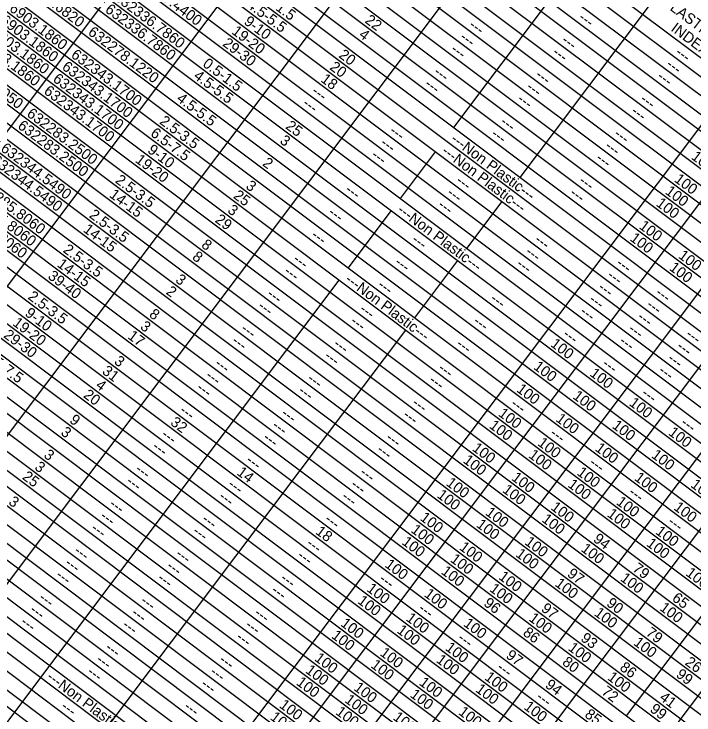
# Model space of a CAD drawing. Extents: x 627484.2 to 627517.5, y 367968.7 to 367996.9.
# Drawn here: x 627492.236 to 627495.744, y 367986.94 to 367990.557 of the extents above; entities that cross this region are included whole.
import ezdxf

# ---------------------------------------------------------------- set-up
doc = ezdxf.new("R2010")
doc.units = 0
doc.layers.add('Default', color=7, linetype='Continuous')

msp = doc.modelspace()

# ---------------------------------------------------------------- linework, layer by layer
at = {"layer": 'Default'}
for p, q in [((627492.9586, 367992.4496), (627498.2015, 367988.5126)), ((627492.9118, 367992.3872), (627498.1547, 367988.4503)), ((627492.8649, 367992.3248), (627498.1078, 367988.3879)), ((627492.8181, 367992.2625), (627498.061, 367988.3255)), ((627492.7771, 367992.2079), (627498.02, 367988.2709)), ((627492.7303, 367992.1455), (627497.9732, 367988.2086)), ((627490.4128, 367987.5698), (627493.8348, 367992.127)), ((627492.6834, 367992.0832), (627497.9263, 367988.1462)), ((627492.6425, 367992.0286), (627497.8854, 367988.0916)), ((627492.5956, 367991.9662), (627497.8385, 367988.0293)), ((627492.5488, 367991.9038), (627497.7917, 367987.9669)), ((627490.7966, 367987.2816), (627494.2186, 367991.8387)), ((627492.5019, 367991.8415), (627497.7449, 367987.9045)), ((627492.461, 367991.7869), (627497.7039, 367987.8499)), ((627492.4141, 367991.7245), (627497.657, 367987.7876)), ((627492.3673, 367991.6621), (627497.6102, 367987.7252)), ((627492.3263, 367991.6076), (627497.5692, 367987.6706)), ((627492.6599, 367988.9917), (627494.589, 367991.5606)), ((627492.2795, 367991.5452), (627497.5224, 367987.6082)), ((627492.2326, 367991.4828), (627497.4755, 367987.5459)), ((627492.1858, 367991.4204), (627497.4287, 367987.4835)), ((627492.139, 367991.3581), (627497.3819, 367987.4211)), ((627492.0921, 367991.2957), (627497.335, 367987.3587)), ((627493.0263, 367988.7165), (627494.9554, 367991.2855)), ((627492.0511, 367991.2411), (627497.2941, 367987.3042)), ((627492.0043, 367991.1787), (627497.2472, 367987.2418)), ((627491.9575, 367991.1164), (627497.2004, 367987.1794)), ((627491.9165, 367991.0618), (627497.1594, 367987.1248)), ((627491.8697, 367990.9994), (627497.1126, 367987.0625)), ((627494.5052, 367989.9714), (627495.2428, 367990.9538)), ((627491.8287, 367990.9448), (627497.0716, 367987.0079)), ((627491.7818, 367990.8825), (627497.0247, 367986.9455)), ((627491.735, 367990.8201), (627496.9779, 367986.8832)), ((627491.6882, 367990.7577), (627496.9311, 367986.8208)), ((627491.6413, 367990.6954), (627496.8842, 367986.7584)), ((627494.8482, 367989.7138), (627495.5859, 367990.6962)), ((627491.6003, 367990.6408), (627496.8433, 367986.7038)), ((627491.5535, 367990.5784), (627496.7964, 367986.6415)), ((627491.5067, 367990.516), (627496.7496, 367986.5791)), ((627491.4657, 367990.4615), (627496.7086, 367986.5245)), ((627494.1802, 367987.85), (627496.1093, 367990.419)), ((627491.4189, 367990.3991), (627496.6618, 367986.4621)), ((627491.372, 367990.3367), (627496.6149, 367986.3998)), ((627491.331, 367990.2821), (627496.5739, 367986.3452)), ((627491.2842, 367990.2198), (627496.5271, 367986.2828)), ((627491.2374, 367990.1574), (627496.4803, 367986.2204)), ((627494.3673, 367987.7095), (627496.191, 367990.1382)), ((627491.1905, 367990.095), (627496.4334, 367986.1581)), ((627491.1495, 367990.0404), (627496.3925, 367986.1035)), ((627491.1027, 367989.9781), (627496.3456, 367986.0411)), ((627494.5856, 367987.5456), (627496.4093, 367989.9742)), ((627491.0559, 367989.9157), (627496.2988, 367985.9787)), ((627491.009, 367989.8533), (627496.2519, 367985.9164)), ((627494.23, 367989.605), (627494.4115, 367989.8467)), ((627494.7728, 367987.4051), (627496.5965, 367989.8337)), ((627490.9622, 367989.791), (627496.2051, 367985.854)), ((627490.9212, 367989.7364), (627496.1641, 367985.7994)), ((627490.8744, 367989.674), (627496.1173, 367985.7371)), ((627494.9911, 367987.2412), (627496.8148, 367989.6698)), ((627490.8275, 367989.6116), (627496.0705, 367985.6747)), ((627494.573, 367989.3474), (627494.7545, 367989.5891)), ((627490.7866, 367989.5571), (627496.0295, 367985.6201)), ((627493.9607, 367989.2464), (627494.1832, 367989.5426)), ((627495.1782, 367987.1006), (627497.0019, 367989.5293)), ((627490.7397, 367989.4947), (627495.9826, 367985.5577)), ((627490.6929, 367989.4323), (627495.9358, 367985.4954)), ((627490.6461, 367989.3699), (627495.889, 367985.433)), ((627495.3965, 367986.9367), (627497.2202, 367989.3654)), ((627490.6051, 367989.3154), (627495.848, 367985.3784)), ((627494.3037, 367988.9888), (627494.5262, 367989.285)), ((627490.5582, 367989.253), (627495.8011, 367985.316)), ((627495.5836, 367986.7962), (627497.4073, 367989.2249)), ((627490.5114, 367989.1906), (627495.7543, 367985.2537)), ((627493.3694, 367988.4589), (627493.9138, 367989.184)), ((627490.4646, 367989.1282), (627495.7075, 367985.1913)), ((627490.4236, 367989.0737), (627495.6665, 367985.1367)), ((627490.3767, 367989.0113), (627495.6197, 367985.0743)), ((627491.167, 367987.0035), (627492.6599, 367988.9917)), ((627490.3299, 367988.9489), (627495.5728, 367985.012)), ((627493.7124, 367988.2013), (627494.2569, 367988.9264)), ((627490.2831, 367988.8865), (627495.526, 367984.9496)), ((627490.2421, 367988.832), (627495.485, 367984.895)), ((627490.1953, 367988.7696), (627495.4382, 367984.8326)), ((627490.1484, 367988.7072), (627495.3913, 367984.7703)), ((627491.5334, 367986.7284), (627493.0263, 367988.7165)), ((627490.1016, 367988.6449), (627495.3445, 367984.7079)), ((627490.0606, 367988.5903), (627495.3035, 367984.6533)), ((627492.3741, 367987.1335), (627493.3694, 367988.4589)), ((627492.7172, 367986.8759), (627493.7124, 367988.2013)), ((627492.6873, 367985.8619), (627494.1802, 367987.85)), ((627492.8744, 367985.7214), (627494.3673, 367987.7095)), ((627493.0927, 367985.5575), (627494.5856, 367987.5456)), ((627493.2799, 367985.417), (627494.7728, 367987.4051)), ((627493.4982, 367985.253), (627494.9911, 367987.2412)), ((627491.8765, 367986.4708), (627492.3741, 367987.1335)), ((627493.6853, 367985.1125), (627495.1782, 367987.1006))]:
    msp.add_line(p, q, dxfattribs=at)

# ---------------------------------------------------------------- texts
for s, p in [('376485.6820', (627492.2304, 367990.7429)), ('632337.4400', (627492.8367, 367990.751)), ('0.5-1.5', (627493.4807, 367990.6576)), ('376903.1860', (627492.1426, 367990.626)), ('632336.7860', (627492.7489, 367990.634)), ('4.5-5.5', (627493.4338, 367990.5952)), ('PLASTICITY', (627495.5769, 367990.6104)), ('376903.1860', (627492.0958, 367990.5636)), ('632336.7860', (627492.7021, 367990.5716)), ('22', (627494.0425, 367990.5162)), ('---', (627495.1442, 367990.5302)), ('376903.1860', (627492.0489, 367990.5012)), ('9-10', (627493.4185, 367990.5092)), ('INDEX', (627495.6212, 367990.474)), ('376903.1860', (627492.0021, 367990.4388)), ('632278.1220', (627492.6142, 367990.4547)), ('19-20', (627493.3554, 367990.459)), ('---', (627494.5787, 367990.4915)), ('4', (627494.0116, 367990.4417)), ('---', (627494.5318, 367990.4291)), ('29-30', (627493.3086, 367990.3966)), ('---', (627495.0564, 367990.4132)), ('632343.1700', (627492.5264, 367990.3377)), ('20', (627493.9076, 367990.337)), ('---', (627494.485, 367990.3667)), ('---', (627495.0095, 367990.3508)), ('---', (627495.6433, 367990.3505)), ('377005.8050', (627491.9143, 367990.3219)), ('632343.1700', (627492.4796, 367990.2754)), ('0.5-1.5', (627493.2055, 367990.2911)), ('20', (627493.8608, 367990.2746)), ('---', (627495.5964, 367990.2881)), ('---', (627494.3972, 367990.2498)), ('632343.1700', (627492.4327, 367990.213)), ('4.5-5.5', (627493.1587, 367990.2288)), ('18', (627493.8146, 367990.2117)), ('---', (627494.9217, 367990.2339)), ('---', (627495.5496, 367990.2257)), ('632343.1700', (627492.3859, 367990.1506)), ('---', (627494.3503, 367990.1874)), ('---', (627494.8749, 367990.1715)), ('---', (627493.7673, 367990.1497)), ('4.5-5.5', (627493.0709, 367990.1118)), ('---', (627494.828, 367990.1091)), ('---', (627495.4618, 367990.1088)), ('---', (627493.7204, 367990.0874)), ('632283.2500', (627492.2981, 367990.0337)), ('---', (627495.415, 367990.0464)), ('632283.2500', (627492.2513, 367989.9713)), ('2.5-3.5', (627492.983, 367989.9949)), ('25', (627493.6334, 367989.9698)), ('---', (627494.7402, 367989.9922)), ('6.5-7.5', (627492.9362, 367989.9325)), ('---', (627494.1688, 367989.9457)), ('---', (627494.6934, 367989.9298)), ('---', (627495.3271, 367989.9295)), ('3', (627493.6034, 367989.8948)), ('---', (627494.122, 367989.8834)), ('---Non Plastic---', (627494.4848, 367989.9036)), ('632344.5490', (627492.1634, 367989.8544)), ('9-10', (627492.9209, 367989.8465)), ('---', (627495.2803, 367989.8671)), ('632344.5490', (627492.1166, 367989.792)), ('19-20', (627492.8578, 367989.7963)), ('---', (627494.0752, 367989.821)), ('---Non Plastic---', (627494.438, 367989.8412)), ('100', (627495.726, 367989.8128)), ('2', (627493.5142, 367989.7789)), ('---', (627495.2335, 367989.8047)), ('2.5-3.5', (627492.7547, 367989.6908)), ('100', (627495.6382, 367989.6959)), ('632285.8060', (627492.0288, 367989.675)), ('3', (627493.4278, 367989.6609)), ('---', (627494.5119, 367989.6881)), ('---', (627495.1457, 367989.6878)), ('632285.8060', (627491.9819, 367989.6127)), ('14-15', (627492.7241, 367989.6162)), ('25', (627493.3641, 367989.6112)), ('---', (627493.9405, 367989.6417)), ('---', (627494.4651, 367989.6258)), ('100', (627495.5914, 367989.6335)), ('---', (627495.0988, 367989.6254)), ('632285.8060', (627491.9351, 367989.5503)), ('3', (627493.3341, 367989.5362)), ('---', (627494.4182, 367989.5634)), ('100', (627495.5445, 367989.5711)), ('2.5-3.5', (627492.6201, 367989.5115)), ('---', (627493.8527, 367989.5247)), ('---Non Plastic---', (627494.2096, 367989.5371)), ('29', (627493.2697, 367989.487)), ('14-15', (627492.5894, 367989.4369)), ('100', (627495.4567, 367989.4542)), ('8', (627493.1986, 367989.3575)), ('---', (627493.7649, 367989.4078)), ('---', (627494.2836, 367989.3841)), ('---', (627494.9173, 367989.3837)), ('100', (627495.4099, 367989.3918)), ('2.5-3.5', (627492.4854, 367989.3322)), ('8', (627493.1518, 367989.2951)), ('---', (627494.8705, 367989.3213)), ('100', (627495.6594, 367989.302)), ('14-15', (627492.4548, 367989.2576)), ('---', (627493.6712, 367989.283)), ('---', (627494.1958, 367989.2671)), ('---', (627494.8237, 367989.2589)), ('---', (627495.3385, 367989.2625)), ('100', (627495.6126, 367989.2396)), ('39-40', (627492.407, 367989.196)), ('3', (627493.0648, 367989.1775)), ('---', (627493.6244, 367989.2206)), ('---', (627495.2916, 367989.2002)), ('---Non Plastic---', (627493.9403, 367989.1785)), ('2', (627493.0166, 367989.1162)), ('---', (627494.1079, 367989.1502)), ('---', (627495.2448, 367989.1378)), ('2.5-3.5', (627492.3039, 367989.0905)), ('---', (627493.5366, 367989.1037)), ('---', (627495.5412, 367989.1103)), ('---', (627494.689, 367989.0796)), ('---', (627495.1979, 367989.0754)), ('---', (627495.4943, 367989.048)), ('9-10', (627492.2886, 367989.0044)), ('8', (627492.9293, 367988.9988)), ('---', (627493.4897, 367989.0413)), ('---', (627494.0143, 367989.0254)), ('---', (627495.1511, 367989.0131)), ('---', (627495.4475, 367988.9856)), ('19-20', (627492.2255, 367988.9543)), ('3', (627492.8833, 367988.9358)), ('---', (627493.9674, 367988.963)), ('---', (627494.6012, 367988.9627)), ('29-30', (627492.1786, 367988.8919)), ('---', (627493.4019, 367988.9244)), ('---', (627495.4007, 367988.9232)), ('17', (627492.819, 367988.8866)), ('---', (627495.0633, 367988.8961)), ('---', (627495.697, 367988.8957)), ('---', (627493.3551, 367988.862)), ('---', (627493.8796, 367988.8461)), ('---', (627494.5134, 367988.8457)), ('100', (627495, 367988.8461)), ('---', (627495.3538, 367988.8608)), ('---', (627495.6502, 367988.8334)), ('6.5-7.5', (627492.0756, 367988.7864)), ('3', (627492.7487, 367988.7565)), ('---', (627493.8328, 367988.7837)), ('---', (627495.6034, 367988.771)), ('31', (627492.6868, 367988.7054)), ('---', (627493.2673, 367988.7451)), ('100', (627494.9122, 367988.7291)), ('---', (627495.266, 367988.7439)), ('---', (627494.4197, 367988.721)), ('100', (627495.2028, 367988.6938)), ('---', (627495.5565, 367988.7086)), ('---', (627493.2204, 367988.6827)), ('---', (627493.745, 367988.6668)), ('---', (627494.3729, 367988.6586)), ('4', (627492.6534, 367988.6329)), ('---', (627493.1736, 367988.6203)), ('100', (627494.8244, 367988.6122)), ('20', (627492.5903, 367988.5827)), ('---', (627493.6981, 367988.6044)), ('100', (627495.1149, 367988.5769)), ('---', (627495.4687, 367988.5917)), ('---', (627494.285, 367988.5417)), ('100', (627495.4055, 367988.5416)), ('---', (627494.794, 367988.5375)), ('9', (627492.519, 367988.4534)), ('---', (627493.0858, 367988.5034)), ('---', (627493.6103, 367988.4875)), ('---', (627494.2382, 367988.4793)), ('100', (627494.7307, 367988.4874)), ('100', (627495.0271, 367988.4599)), ('32', (627493.039, 367988.441)), ('100', (627494.6839, 367988.425)), ('100', (627495.3177, 367988.4247)), ('---', (627495.6714, 367988.4395)), ('3', (627492.4735, 367988.3901)), ('---', (627493.5635, 367988.4251)), ('100', (627495.6082, 367988.3894)), ('---', (627492.9921, 367988.3786)), ('---', (627493.5166, 367988.3627)), ('---', (627494.1504, 367988.3623)), ('---', (627494.9967, 367988.3852)), ('100', (627494.9335, 367988.3352)), ('3', (627492.3857, 367988.2731)), ('---', (627492.9453, 367988.3162)), ('---', (627494.1035, 367988.3)), ('100', (627494.5961, 367988.3081)), ('100', (627494.8866, 367988.2728)), ('100', (627495.2298, 367988.3077)), ('100', (627495.5204, 367988.2725)), ('100', (627494.5492, 367988.2457)), ('3', (627492.3388, 367988.2107)), ('---', (627493.4288, 367988.2458)), ('---', (627495.1994, 367988.233)), ('25', (627492.2752, 367988.161)), ('---', (627492.8574, 367988.1993)), ('14', (627493.3818, 367988.1835)), ('---', (627494.0157, 367988.183)), ('100', (627495.1362, 367988.183)), ('100', (627494.4614, 367988.1288)), ('100', (627494.7988, 367988.1559)), ('100', (627495.4325, 367988.1555)), ('---', (627492.8106, 367988.1369)), ('---', (627493.3351, 367988.121)), ('---', (627493.9689, 367988.1206)), ('100', (627494.752, 367988.0935)), ('100', (627495.0893, 367988.1206)), ('100', (627495.7231, 367988.1202)), ('100', (627494.4146, 367988.0664)), ('---', (627495.4021, 367988.0808)), ('3', (627492.2042, 367988.0314)), ('---', (627493.2883, 367988.0586)), ('---', (627493.9221, 367988.0583)), ('100', (627495.3389, 367988.0308)), ('---', (627492.7228, 367988.02)), ('100', (627495.0015, 367988.0037)), ('100', (627495.6353, 367988.0033)), ('100', (627494.3268, 367987.9494)), ('100', (627494.6641, 367987.9765)), ('100', (627495.292, 367987.9684)), ('---', (627492.6759, 367987.9576)), ('---', (627493.2005, 367987.9417)), ('---', (627493.8342, 367987.9413)), ('100', (627494.6173, 367987.9142)), ('100', (627494.9547, 367987.9413)), ('---', (627495.6048, 367987.9286)), ('---', (627492.6291, 367987.8952)), ('18', (627493.7879, 367987.8785)), ('100', (627494.2799, 367987.8871)), ('100', (627495.5416, 367987.8785)), ('---', (627493.1536, 367987.8793)), ('94', (627495.2204, 367987.8393)), ('100', (627494.2331, 367987.8247)), ('100', (627494.8669, 367987.8243)), ('100', (627495.4947, 367987.8162)), ('---', (627493.7406, 367987.8166)), ('100', (627494.5295, 367987.7972)), ('100', (627495.1574, 367987.7891)), ('---', (627492.5413, 367987.7783)), ('---', (627493.0658, 367987.7624)), ('---', (627493.6937, 367987.7542)), ('100', (627494.4827, 367987.7349)), ('100', (627494.82, 367987.762)), ('---', (627492.4945, 367987.7159)), ('100', (627494.1453, 367987.7078)), ('79', (627495.4234, 367987.6868)), ('---', (627493.019, 367987.7)), ('100', (627494.4358, 367987.6725)), ('97', (627495.0861, 367987.6597)), ('100', (627495.6975, 367987.6639)), ('---', (627492.4476, 367987.6535)), ('---', (627492.9722, 367987.6376)), ('---', (627493.6059, 367987.6373)), ('100', (627494.7322, 367987.645)), ('100', (627495.3601, 367987.6368)), ('---', (627494.1149, 367987.6331)), ('100', (627495.0227, 367987.6097)), ('---', (627493.5591, 367987.5749)), ('100', (627494.0516, 367987.583)), ('100', (627494.348, 367987.5555)), ('100', (627494.6854, 367987.5826)), ('---', (627492.3598, 367987.5366)), ('100', (627494.0048, 367987.5206)), ('96', (627494.6549, 367987.508)), ('65', (627495.6269, 367987.5341)), ('---', (627492.8843, 367987.5207)), ('97', (627494.9515, 367987.4804)), ('90', (627495.2885, 367987.5077)), ('100', (627495.5628, 367987.4846)), ('---', (627492.313, 367987.4742)), ('---', (627492.8375, 367987.4583)), ('---', (627493.4713, 367987.4579)), ('---', (627494.3176, 367987.4808)), ('100', (627495.2254, 367987.4575)), ('100', (627494.2543, 367987.4308)), ('100', (627494.8881, 367987.4304)), ('---', (627492.2661, 367987.4118)), ('---', (627492.7907, 367987.3959)), ('---', (627493.4244, 367987.3956)), ('100', (627493.917, 367987.4037)), ('100', (627494.2075, 367987.3684)), ('100', (627494.5507, 367987.4033)), ('100', (627493.8701, 367987.3413)), ('86', (627494.8576, 367987.3558)), ('93', (627495.1554, 367987.3272)), ('79', (627495.4915, 367987.3553)), ('---', (627493.3776, 367987.3332)), ('---', (627494.5203, 367987.3286)), ('100', (627495.4282, 367987.3053)), ('---', (627492.7028, 367987.279)), ('100', (627494.457, 367987.2786)), ('100', (627495.0908, 367987.2782)), ('100', (627493.7823, 367987.2244)), ('100', (627494.1197, 367987.2515)), ('97', (627494.77, 367987.2387)), ('---', (627492.656, 367987.2166)), ('---', (627493.2898, 367987.2162)), ('100', (627494.0728, 367987.1891)), ('100', (627494.4102, 367987.2162)), ('80', (627495.0602, 367987.2036)), ('26', (627495.694, 367987.2032)), ('100', (627493.7355, 367987.162)), ('---', (627494.723, 367987.1764)), ('86', (627495.3567, 367987.1761)), ('---', (627492.6092, 367987.1542)), ('---', (627493.2429, 367987.1539)), ('100', (627494.6597, 367987.1264)), ('100', (627495.2935, 367987.126)), ('99', (627495.6473, 367987.1407)), ('---Non Plastic---', (627492.4006, 367987.128)), ('100', (627493.6886, 367987.0996)), ('100', (627494.3224, 367987.0992)), ('94', (627494.9723, 367987.0867)), ('---', (627493.1961, 367987.0915)), ('100', (627493.985, 367987.0721)), ('100', (627494.6129, 367987.064)), ('72', (627495.2631, 367987.0513)), ('100', (627493.9382, 367987.0098)), ('100', (627494.2755, 367987.0369)), ('---', (627494.9257, 367987.0242)), ('41', (627495.5621, 367987.0218)), ('100', (627493.6008, 367986.9827)), ('100', (627494.8625, 367986.9741)), ('---', (627492.4745, 367986.9749)), ('---', (627493.1083, 367986.9745)), ('100', (627493.8913, 367986.9474)), ('100', (627494.5251, 367986.947)), ('85', (627495.1761, 367986.9337)), ('99', (627495.5127, 367986.9614)), ('100', (627493.554, 367986.9203)), ('100', (627494.1877, 367986.9199))]:
    msp.add_text(s, height=0.055, rotation=323.0968, dxfattribs=at).set_placement(p)

doc.saveas('drawing.dxf')
